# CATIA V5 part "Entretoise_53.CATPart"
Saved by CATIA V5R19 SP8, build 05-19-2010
Part number: Entretoise_61
Bounding box of the stored display mesh (mm): x -19 to 19, y -18.807 to 18.807, z 0 to 61
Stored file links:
  G:\EU_thinkMotion\CFAO_2010\MMS_groupe1\MMS_groupe1\OK\vduret\vduret\CATIA\Entretoise_53.CATPart
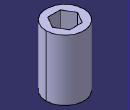
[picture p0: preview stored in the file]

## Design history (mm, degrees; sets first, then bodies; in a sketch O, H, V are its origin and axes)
Body1 (main body)
  Sketch1 on xy-plane, origin (0, 0, 0), H (1, 0, 0), V (0, 1, 0)
    circle A1 centre (0, 0) radius 19
    point P1 (0, 0)
    point P2 (6.3509, -11)
    point P3 (12.7017, 0)
    point P4 (6.3509, 11)
    point P5 (-6.3509, 11)
    point P6 (-12.7017, 0)
    point P7 (-6.3509, -11)
    point P8 (9.5263, -5.5)
    line L1 (6.3509, -11) -> (12.7017, 0)
    line L2 (12.7017, 0) -> (6.3509, 11)
    line L3 (6.3509, 11) -> (-6.3509, 11)
    line L4 (-6.3509, 11) -> (-12.7017, 0)
    line L5 (-12.7017, 0) -> (-6.3509, -11)
    line L6 (-6.3509, -11) -> (6.3509, -11)
    construction line L7 (0, 0) -> (9.5263, -5.5)
    construction circle A2 centre (0, 0) radius 12.7017
    construction arc A3 centre (-12.7017, 0) radius 12.7017 from (-6.3509, 11) to (-6.3509, -11) cw
    construction arc A4 centre (12.7017, 0) radius 12.7017 from (6.3509, 11) to (6.3509, -11) ccw
    radius A1 = 19
    distance L3 L6 = 22
    coincidence: A2 P2, A2 P3, A2 P4, A2 P5, A2 P6, A2 P7, A3 P1, A4 P1, P1 O
    midpoint: P8 L1
    parallelism: L1 L4
    horizontal: L3 H
  Pad1: profile Sketch1, direction (0, 0, 1), length 61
